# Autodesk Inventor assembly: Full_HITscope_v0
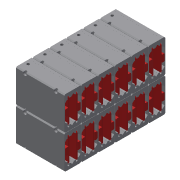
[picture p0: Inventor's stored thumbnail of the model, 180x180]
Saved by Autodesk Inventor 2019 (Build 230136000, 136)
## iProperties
Created: 2021-09
Part Number: Full_HITscope_v0
Material: Generisch
Document SubType Name: Assembly
Designer: Muriel
Author: Muriel
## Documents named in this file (2)
- C:\Users\Muriel\Documents\Inventor\HITscope\Full_HITscope_v0.iam
- C:\Users\Muriel\Documents\Inventor\HITscope\Assembly_HITscope.iam
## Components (12 placed, 1 different names)
1. Assembly_HITscope:1 [sub-assembly]
2. Assembly_HITscope:2 [sub-assembly]
3. Assembly_HITscope:3 [sub-assembly]
4. Assembly_HITscope:4 [sub-assembly]
5. Assembly_HITscope:5 [sub-assembly]
6. Assembly_HITscope:6 [sub-assembly]
7. Assembly_HITscope:7 [sub-assembly]
8. Assembly_HITscope:8 [sub-assembly]
9. Assembly_HITscope:9 [sub-assembly]
10. Assembly_HITscope:10 [sub-assembly]
11. Assembly_HITscope:11 [sub-assembly]
12. Assembly_HITscope:12 [sub-assembly]
